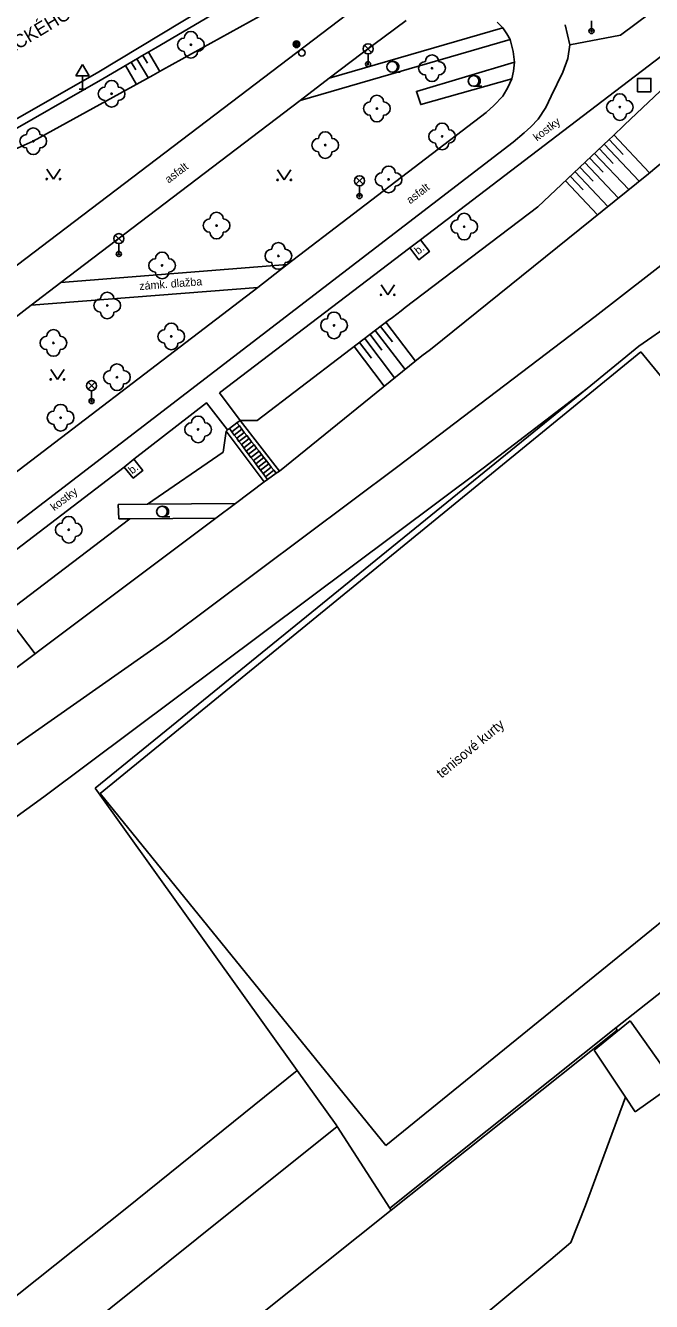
# Model space of a CAD drawing. Extents: x -493753 to -49290, y -1127285 to -112654.
# Drawn here: x -493017.9 to -492971, y -1126683.6 to -1126587.9 of the extents above; entities that cross this region are included whole.
import ezdxf

# ---------------------------------------------------------------- set-up
doc = ezdxf.new("R2010")
doc.units = 0
for name, color, linetype in [('Vrstva 10', 7, 'Continuous'), ('Vrstva 11', 7, 'Continuous'), ('Vrstva 14', 7, 'Continuous'), ('Vrstva 15', 7, 'Continuous'), ('Vrstva 21', 7, 'Continuous'), ('Vrstva 22', 7, 'Continuous'), ('Vrstva 23', 7, 'Continuous'), ('Vrstva 25', 7, 'Continuous'), ('Vrstva 26', 7, 'Continuous'), ('Vrstva 31', 7, 'Continuous'), ('Vrstva 33', 7, 'Continuous'), ('Vrstva 34', 7, 'Continuous'), ('Vrstva 36', 7, 'Continuous'), ('Vrstva 40', 7, 'Continuous'), ('Vrstva 42', 7, 'Continuous'), ('Vrstva 45', 7, 'Continuous'), ('Vrstva 7', 7, 'Continuous'), ('Vrstva 8', 7, 'Continuous')]:
    doc.layers.add(name, color=color, linetype=linetype)

msp = doc.modelspace()

# ---------------------------------------------------------------- linework, layer by layer
at = {"layer": 'Vrstva 10'}
for p, q in [((-493012.38, -1126591.4), (-493000.12, -1126584)), ((-492992.66, -1126590), (-492989.36, -1126587.55)), ((-492967.32, -1126588), (-492988.29, -1126603.99)), ((-492982.54, -1126587.69), (-492982.12, -1126588.12)), ((-492995.12, -1126591.89), (-492992.66, -1126590)), ((-493024.41, -1126598.28), (-493012.38, -1126591.4)), ((-492981.45, -1126591.94), (-492981.73, -1126592.58)), ((-492982.11, -1126593.22), (-492982.78, -1126593.94)), ((-492981.73, -1126592.58), (-492982.11, -1126593.22)), ((-492982.78, -1126593.94), (-492983.37, -1126594.45)), ((-492983.37, -1126594.45), (-492998.28, -1126605.86)), ((-492989.09, -1126604.61), (-493003.34, -1126615.47)), ((-492998.28, -1126605.86), (-493015.22, -1126607.19)), ((-493017.45, -1126608.89), (-493000.48, -1126607.56)), ((-493003.34, -1126615.47), (-493001.79, -1126617.53))]:
    msp.add_line(p, q, dxfattribs=at)
for points in [[(-492985.18, -1126582.35), (-492985.89, -1126582.39), (-492986.62, -1126582.55), (-492988.44, -1126583.3), (-492989.31, -1126583.75), (-492990.15, -1126584.3), (-493020.37, -1126607.3), (-493025.91, -1126611.01)], [(-492977.09, -1126589.39), (-492973.31, -1126588.67), (-492966.57, -1126583.61)], [(-492982.12, -1126588.12), (-492981.82, -1126588.55), (-492981.57, -1126588.99)], [(-492977.09, -1126589.39), (-492977.44, -1126587.89)], [(-492981.57, -1126588.99), (-492981.34, -1126589.88), (-492981.24, -1126590.69)], [(-492981.24, -1126590.69), (-492981.31, -1126591.36), (-492981.45, -1126591.94)], [(-492997.3, -1126593.55), (-492995.12, -1126591.89)], [(-493015.22, -1126607.19), (-492997.3, -1126593.55)], [(-492989.09, -1126604.61), (-492988.41, -1126605.49), (-492987.62, -1126604.88), (-492988.29, -1126603.99)], [(-493000.48, -1126607.56), (-493022.39, -1126624.3)], [(-493034.86, -1126621.08), (-493024.36, -1126614.13), (-493022.77, -1126612.99), (-493017.45, -1126608.89)], [(-492990.89, -1126671.88), (-493012.27, -1126645.51), (-492971.77, -1126612.39)], [(-492971.77, -1126612.39), (-492950.15, -1126638.81), (-492990.89, -1126671.88)], [(-493002.73, -1126618.25), (-493004.31, -1126616.22), (-493009.75, -1126620.45)], [(-493001.79, -1126617.53), (-492998.85, -1126621.33)], [(-493002.83, -1126618.33), (-493002.73, -1126618.25)], [(-492999.99, -1126622.14), (-493002.83, -1126618.33)], [(-493010.47, -1126621.03), (-493009.8, -1126621.86), (-493009.08, -1126621.28), (-493009.75, -1126620.45)], [(-493010.47, -1126621.03), (-493030.36, -1126636.24)], [(-492999.1, -1126621.5), (-492999.75, -1126621.97), (-492999.99, -1126622.14)], [(-492998.85, -1126621.33), (-492999.1, -1126621.5)]]:
    msp.add_lwpolyline(points, dxfattribs=at)
at = {"layer": 'Vrstva 11'}
for p, q in [((-492977.24, -1126590.4), (-492977.09, -1126589.39)), ((-492977.63, -1126591.43), (-492977.24, -1126590.4)), ((-492978.49, -1126593.23), (-492977.63, -1126591.43)), ((-492978.9, -1126594.08), (-492978.49, -1126593.23)), ((-492979.47, -1126594.96), (-492978.9, -1126594.08)), ((-492980.01, -1126595.52), (-492979.47, -1126594.96)), ((-492981.34, -1126596.68), (-492980.51, -1126595.98)), ((-492980.51, -1126595.98), (-492980.01, -1126595.52)), ((-493028.5, -1126632.89), (-492981.34, -1126596.68)), ((-493002.41, -1126618.39), (-493001.84, -1126617.95)), ((-493001.66, -1126618.19), (-493002.23, -1126618.63)), ((-493002.05, -1126618.87), (-493001.48, -1126618.43)), ((-493001.29, -1126618.66), (-493001.88, -1126619.11)), ((-493001.7, -1126619.35), (-493001.11, -1126618.9)), ((-493000.56, -1126619.61), (-493001.16, -1126620.07)), ((-493000.98, -1126620.31), (-493000.38, -1126619.85)), ((-493000.19, -1126620.09), (-493000.8, -1126620.55)), ((-493000.62, -1126620.79), (-493000.01, -1126620.32)), ((-492999.83, -1126620.56), (-493000.44, -1126621.03)), ((-493000.26, -1126621.27), (-492999.64, -1126620.8)), ((-492999.46, -1126621.04), (-493000.08, -1126621.52)), ((-492999.9, -1126621.76), (-492999.27, -1126621.27))]:
    msp.add_line(p, q, dxfattribs=at)
for points in [[(-492988.29, -1126603.99), (-492989.09, -1126604.61)], [(-492998.28, -1126605.86), (-493000.48, -1126607.56)], [(-493017.45, -1126608.89), (-493015.22, -1126607.19)], [(-492983.59, -1126621.11), (-492975.79, -1126615.13)], [(-493002.73, -1126618.25), (-493002.59, -1126618.15), (-493002.03, -1126617.71), (-493001.79, -1126617.53)], [(-493002.59, -1126618.15), (-493002.41, -1126618.39), (-493002.23, -1126618.63), (-493002.05, -1126618.87), (-493001.88, -1126619.11), (-493001.7, -1126619.35), (-493001.52, -1126619.59), (-493001.34, -1126619.83), (-493001.16, -1126620.07), (-493000.98, -1126620.31), (-493000.8, -1126620.55), (-493000.62, -1126620.79), (-493000.44, -1126621.03), (-493000.26, -1126621.27), (-493000.08, -1126621.52), (-492999.9, -1126621.76), (-492999.75, -1126621.97)], [(-492999.1, -1126621.5), (-492999.27, -1126621.27), (-492999.46, -1126621.04), (-492999.64, -1126620.8), (-492999.83, -1126620.56), (-493000.01, -1126620.32), (-493000.19, -1126620.09), (-493000.38, -1126619.85), (-493000.56, -1126619.61), (-493000.74, -1126619.37), (-493000.93, -1126619.14), (-493001.11, -1126618.9), (-493001.29, -1126618.66), (-493001.48, -1126618.43), (-493001.66, -1126618.19), (-493001.84, -1126617.95), (-493002.03, -1126617.71)], [(-493000.93, -1126619.14), (-493001.52, -1126619.59)], [(-493001.34, -1126619.83), (-493000.74, -1126619.37)], [(-493009.75, -1126620.45), (-493010.47, -1126621.03)], [(-493016.5, -1126645.75), (-492983.59, -1126621.11)], [(-493023.17, -1126650.58), (-493016.5, -1126645.75)], [(-492975.26, -1126664.73), (-492972.58, -1126662.53)], [(-492972.58, -1126662.53), (-492969.22, -1126667.25)], [(-492975.26, -1126664.73), (-492972.93, -1126668.26)], [(-493010.29, -1126676.56), (-492997.52, -1126666.25)], [(-492969.7, -1126667.59), (-492972.19, -1126669.37)], [(-492972.93, -1126668.26), (-492975.93, -1126676.38), (-492977.03, -1126679.16), (-492978.53, -1126680.44)], [(-492972.19, -1126669.37), (-492972.93, -1126668.26)], [(-492994.52, -1126670.47), (-493005.05, -1126678.87)], [(-493010.29, -1126676.56), (-493036.05, -1126697.08)], [(-493005.56, -1126688.78), (-492990.47, -1126676.73)], [(-493005.05, -1126678.87), (-493026.67, -1126696.23)], [(-492978.53, -1126680.44), (-492990.17, -1126690.14), (-492997.84, -1126696.72), (-493009.15, -1126700.35), (-493023.88, -1126704.92)]]:
    msp.add_lwpolyline(points, dxfattribs=at)
at = {"layer": 'Vrstva 14'}
for points in [[(-492982.18, -1126573), (-492987.04, -1126578.23), (-492987.89, -1126578.82), (-492988.55, -1126579.27), (-492995.54, -1126584.11), (-492996.22, -1126584.53), (-492998.92, -1126586.45), (-493007.61, -1126591.25), (-493008.3, -1126591.66), (-493017.29, -1126596.61), (-493019.76, -1126597.71), (-493020.5, -1126598.04), (-493023.73, -1126599.48)], [(-493030.36, -1126602.42), (-493021.4, -1126597.27), (-493021.05, -1126597.07), (-493020.7, -1126596.87), (-493020.36, -1126596.67), (-493020.01, -1126596.48), (-493012.09, -1126591.92), (-493009.49, -1126590.41), (-493009.15, -1126590.2), (-493008.8, -1126590), (-493008.46, -1126589.8), (-493008.11, -1126589.6), (-493003.56, -1126586.94)], [(-493001.79, -1126617.53), (-493000.53, -1126617.53), (-492990.7, -1126610.05), (-492990.38, -1126609.81), (-492990.06, -1126609.57), (-492989.74, -1126609.32), (-492989.42, -1126609.08), (-492979.49, -1126601.53), (-492974.16, -1126596.49), (-492973.87, -1126596.22), (-492973.58, -1126595.94), (-492973.29, -1126595.67), (-492973, -1126595.39), (-492966.31, -1126589.07), (-492964.16, -1126588.74)], [(-492998.85, -1126621.33), (-492988.18, -1126612.7), (-492987.54, -1126612.21), (-492971.21, -1126599.04), (-492970.58, -1126598.53), (-492964.89, -1126593.94), (-492962.46, -1126591.8)], [(-493089.62, -1126694.8), (-493086.34, -1126692.42), (-493085.72, -1126691.92), (-493080.25, -1126688), (-493075.98, -1126685.38), (-493052.97, -1126667.87), (-493037.61, -1126656.43), (-493019.04, -1126642.21), (-493007.33, -1126633.97), (-492989.97, -1126620.99), (-492975.2, -1126609.75), (-492962.91, -1126600.21), (-492959, -1126598.1)], [(-493008.74, -1126623.81), (-493003.06, -1126619.91), (-493002.83, -1126618.33)], [(-493002.13, -1126623.75), (-492999.99, -1126622.14)], [(-493003.61, -1126624.85), (-493002.13, -1126623.75)], [(-493068.09, -1126673.3), (-493060.02, -1126667.22), (-493059.41, -1126666.7), (-493048.15, -1126658.29), (-493047.25, -1126657.61), (-493046.61, -1126657.13), (-493034.04, -1126647.7), (-493033.4, -1126647.22), (-493017.32, -1126635.15), (-493016.69, -1126634.67), (-493003.61, -1126624.85)], [(-493010.06, -1126624.9), (-493018.64, -1126631.45), (-493018.96, -1126631.69), (-493019.28, -1126631.93), (-493019.6, -1126632.17), (-493019.91, -1126632.42), (-493029.29, -1126639.56)]]:
    msp.add_lwpolyline(points, dxfattribs=at)
at = {"layer": 'Vrstva 15'}
for p, q in [((-493009.52, -1126590.42), (-493008.67, -1126591.87)), ((-493009.09, -1126590.17), (-493008.74, -1126590.75)), ((-493008.65, -1126589.92), (-493007.8, -1126591.37)), ((-493010.38, -1126590.93), (-493009.55, -1126592.35)), ((-493009.95, -1126590.67), (-493009.61, -1126591.25)), ((-492973.79, -1126596.14), (-492971.12, -1126598.97)), ((-492974.52, -1126596.83), (-492971.9, -1126599.6)), ((-492974.16, -1126596.49), (-492973.1, -1126597.61)), ((-492975.61, -1126597.86), (-492974.59, -1126598.93)), ((-492975.25, -1126597.52), (-492972.68, -1126600.23)), ((-492974.88, -1126597.17), (-492973.85, -1126598.27)), ((-492976.7, -1126598.89), (-492974.25, -1126601.49)), ((-492976.34, -1126598.55), (-492975.34, -1126599.6)), ((-492975.97, -1126598.2), (-492973.47, -1126600.86)), ((-492977.43, -1126599.58), (-492975.03, -1126602.12)), ((-492977.06, -1126599.23), (-492976.09, -1126600.26)), ((-492991.27, -1126610.49), (-492990.38, -1126611.65)), ((-492990.87, -1126610.18), (-492988.66, -1126613.09)), ((-492992.46, -1126611.39), (-492990.22, -1126614.34)), ((-492992.06, -1126611.09), (-492991.17, -1126612.27)), ((-492991.67, -1126610.79), (-492989.44, -1126613.71)), ((-492993.26, -1126612), (-492991, -1126614.97)), ((-492992.86, -1126611.7), (-492991.96, -1126612.88)), ((-493019.42, -1126632.04), (-493017.15, -1126635.02))]:
    msp.add_line(p, q, dxfattribs=at)
at = {"layer": 'Vrstva 21'}
msp.add_line((-492982.12, -1126588.12), (-492995.12, -1126591.89), dxfattribs=at)
msp.add_lwpolyline([(-492981.24, -1126590.69), (-492988.59, -1126592.88), (-492988.26, -1126593.86), (-492981.45, -1126591.94)], dxfattribs=at)
at = {"layer": 'Vrstva 22'}
for centre in [(-493005.48, -1126589.38), (-492987.42, -1126591.14), (-493011.42, -1126593.05), (-492991.55, -1126594.16), (-492973.35, -1126594.05), (-493017.29, -1126596.61), (-492995.42, -1126596.9), (-492986.66, -1126596.25), (-492990.67, -1126599.47), (-493003.56, -1126602.93), (-492985.01, -1126603.01), (-492998.93, -1126605.21), (-493007.64, -1126605.92), (-493011.75, -1126608.92), (-492994.76, -1126610.41), (-493006.95, -1126611.24), (-493015.78, -1126611.73), (-493011.02, -1126614.3), (-493015.24, -1126617.33), (-493004.94, -1126618.21), (-493014.63, -1126625.73)]:
    msp.add_circle(centre, 0.05, dxfattribs=at)
for centre, start, end in [((-493005.48, -1126588.88), 0, 180), ((-493005.98, -1126589.38), 90, 270), ((-493004.98, -1126589.38), 270, 90), ((-493005.48, -1126589.88), 180, 0), ((-492987.42, -1126590.64), 0, 180), ((-492987.92, -1126591.14), 90, 270), ((-492986.92, -1126591.14), 270, 90), ((-493011.42, -1126592.55), 0, 180), ((-492987.42, -1126591.64), 180, 0), ((-493011.92, -1126593.05), 90, 270), ((-493010.92, -1126593.05), 270, 90), ((-492991.55, -1126593.66), 0, 180), ((-492973.35, -1126593.55), 0, 180), ((-493011.42, -1126593.55), 180, 0), ((-492992.05, -1126594.16), 90, 270), ((-492991.05, -1126594.16), 270, 90), ((-492973.85, -1126594.05), 90, 270), ((-492972.85, -1126594.05), 270, 90), ((-492991.55, -1126594.66), 180, 0), ((-492973.35, -1126594.55), 180, 0), ((-493017.79, -1126596.61), 90, 270), ((-493017.29, -1126596.11), 0, 180), ((-493016.79, -1126596.61), 270, 90), ((-492995.42, -1126596.4), 0, 180), ((-492987.16, -1126596.25), 90, 270), ((-492986.66, -1126595.75), 0, 180), ((-492986.16, -1126596.25), 270, 90), ((-493017.29, -1126597.11), 180, 0), ((-492995.92, -1126596.9), 90, 270), ((-492994.92, -1126596.9), 270, 90), ((-492986.66, -1126596.75), 180, 0), ((-492995.42, -1126597.4), 180, 0), ((-492991.17, -1126599.47), 90, 270), ((-492990.67, -1126598.97), 0, 180), ((-492990.17, -1126599.47), 270, 90), ((-492990.67, -1126599.97), 180, 0), ((-493004.06, -1126602.93), 90, 270), ((-493003.56, -1126602.43), 0, 180), ((-493003.06, -1126602.93), 270, 90), ((-492985.51, -1126603.01), 90, 270), ((-492985.01, -1126602.51), 0, 180), ((-492984.51, -1126603.01), 270, 90), ((-493003.56, -1126603.43), 180, 0), ((-492985.01, -1126603.51), 180, 0), ((-492999.43, -1126605.21), 90, 270), ((-492998.93, -1126604.71), 0, 180), ((-492998.43, -1126605.21), 270, 90), ((-493008.14, -1126605.92), 90, 270), ((-493007.64, -1126605.42), 0, 180), ((-493007.14, -1126605.92), 270, 90), ((-492998.93, -1126605.71), 180, 0), ((-493007.64, -1126606.42), 180, 0), ((-493012.25, -1126608.92), 90, 270), ((-493011.75, -1126608.42), 0, 180), ((-493011.25, -1126608.92), 270, 90), ((-493011.75, -1126609.42), 180, 0), ((-492994.76, -1126609.91), 0, 180), ((-493006.95, -1126610.74), 0, 180), ((-492995.26, -1126610.41), 90, 270), ((-492994.26, -1126610.41), 270, 90), ((-493016.28, -1126611.73), 90, 270), ((-493015.78, -1126611.23), 0, 180), ((-493015.28, -1126611.73), 270, 90), ((-493007.45, -1126611.24), 90, 270), ((-493006.45, -1126611.24), 270, 90), ((-492994.76, -1126610.91), 180, 0), ((-493015.78, -1126612.23), 180, 0), ((-493006.95, -1126611.74), 180, 0), ((-493011.02, -1126613.8), 0, 180), ((-493011.52, -1126614.3), 90, 270), ((-493010.52, -1126614.3), 270, 90), ((-493011.02, -1126614.8), 180, 0), ((-493015.74, -1126617.33), 90, 270), ((-493015.24, -1126616.83), 0, 180), ((-493014.74, -1126617.33), 270, 90), ((-493015.24, -1126617.83), 180, 0), ((-493005.44, -1126618.21), 90, 270), ((-493004.94, -1126617.71), 0, 180), ((-493004.44, -1126618.21), 270, 90), ((-493004.94, -1126618.71), 180, 0), ((-493014.63, -1126625.23), 0, 180), ((-493015.13, -1126625.73), 90, 270), ((-493014.13, -1126625.73), 270, 90), ((-493014.63, -1126626.23), 180, 0)]:
    msp.add_arc(centre, 0.5, start, end, dxfattribs=at)
at = {"layer": 'Vrstva 23'}
for p, q in [((-492997.3, -1126593.55), (-492981.57, -1126588.99)), ((-493010.89, -1126624.91), (-493010.92, -1126623.83))]:
    msp.add_line(p, q, dxfattribs=at)
for points in [[(-493010.92, -1126623.83), (-493008.74, -1126623.81), (-493002.13, -1126623.75)], [(-493010.89, -1126624.91), (-493010.06, -1126624.9), (-493003.61, -1126624.85)]]:
    msp.add_lwpolyline(points, dxfattribs=at)
at = {"layer": 'Vrstva 25'}
for radius in [0.25, 0.158, 0.05]:
    msp.add_circle((-492997.57, -1126589.34), radius, dxfattribs=at)
at = {"layer": 'Vrstva 26'}
msp.add_lwpolyline([(-492972.02, -1126592.9), (-492971.02, -1126592.9), (-492971.02, -1126591.9), (-492972.02, -1126591.9)], close=True, dxfattribs=at)
at = {"layer": 'Vrstva 31'}
msp.add_circle((-492997.17, -1126589.98), 0.25, dxfattribs=at)
at = {"layer": 'Vrstva 33'}
for p, q in [((-492975.47, -1126588.35), (-492975.47, -1126587.575)), ((-492992.475, -1126589.415), (-492991.945, -1126589.945)), ((-492992.475, -1126589.945), (-492991.945, -1126589.415)), ((-492992.21, -1126590.83), (-492992.21, -1126590.055)), ((-492993.115, -1126599.305), (-492992.585, -1126599.835)), ((-492993.115, -1126599.835), (-492992.585, -1126599.305)), ((-492992.85, -1126600.72), (-492992.85, -1126599.945)), ((-493011.145, -1126603.645), (-493010.615, -1126604.175)), ((-493011.145, -1126604.175), (-493010.615, -1126603.645)), ((-493010.88, -1126605.06), (-493010.88, -1126604.285)), ((-493013.185, -1126614.665), (-493012.655, -1126615.195)), ((-493013.185, -1126615.195), (-493012.655, -1126614.665)), ((-493012.92, -1126616.08), (-493012.92, -1126615.305))]:
    msp.add_line(p, q, dxfattribs=at)
for centre, radius in [((-492975.47, -1126588.35), 0.19), ((-492975.47, -1126588.35), 0.05), ((-492992.21, -1126589.68), 0.375), ((-492992.21, -1126590.83), 0.19), ((-492992.21, -1126590.83), 0.05), ((-492992.85, -1126599.57), 0.375), ((-492992.85, -1126600.72), 0.19), ((-492992.85, -1126600.72), 0.05), ((-493010.88, -1126603.91), 0.375), ((-493010.88, -1126605.06), 0.19), ((-493010.88, -1126605.06), 0.05), ((-493012.92, -1126614.93), 0.375), ((-493012.92, -1126616.08), 0.19), ((-493012.92, -1126616.08), 0.05)]:
    msp.add_circle(centre, radius, dxfattribs=at)
at = {"layer": 'Vrstva 34'}
for p, q in [((-493014.1, -1126591.7), (-493013.6, -1126590.85)), ((-493013.6, -1126590.85), (-493013.1, -1126591.7)), ((-493014.1, -1126591.7), (-493013.1, -1126591.7)), ((-493013.6, -1126592.7), (-493013.6, -1126591.7)), ((-493013.85, -1126592.7), (-493013.35, -1126592.7))]:
    msp.add_line(p, q, dxfattribs=at)
at = {"layer": 'Vrstva 36'}
for p, q in [((-492990.4, -1126591.43), (-492990.3, -1126591.43)), ((-492990.3, -1126591.43), (-492989.8, -1126591.43)), ((-492984.3, -1126592.49), (-492984.2, -1126592.49)), ((-492984.2, -1126592.49), (-492983.7, -1126592.49)), ((-493016.28, -1126598.69), (-493015.78, -1126599.44)), ((-493015.78, -1126599.44), (-493015.28, -1126598.69)), ((-492998.99, -1126598.76), (-492998.49, -1126599.51)), ((-492998.49, -1126599.51), (-492997.99, -1126598.76)), ((-492991.24, -1126607.37), (-492990.74, -1126608.12)), ((-492990.74, -1126608.12), (-492990.24, -1126607.37)), ((-493015.98, -1126613.71), (-493015.48, -1126614.46)), ((-493015.48, -1126614.46), (-493014.98, -1126613.71)), ((-493007.65, -1126624.77), (-493007.55, -1126624.77)), ((-493007.55, -1126624.77), (-493007.05, -1126624.77))]:
    msp.add_line(p, q, dxfattribs=at)
for centre, radius in [((-492990.4, -1126591.03), 0.4), ((-492984.3, -1126592.09), 0.4), ((-493016.28, -1126599.44), 0.05), ((-493015.28, -1126599.44), 0.05), ((-492998.99, -1126599.51), 0.05), ((-492997.99, -1126599.51), 0.05), ((-492991.24, -1126608.12), 0.05), ((-492990.24, -1126608.12), 0.05), ((-493015.98, -1126614.46), 0.05), ((-493014.98, -1126614.46), 0.05), ((-493007.65, -1126624.37), 0.4)]:
    msp.add_circle(centre, radius, dxfattribs=at)
for centre in [(-492990.3, -1126591.03), (-492984.2, -1126592.09), (-493007.55, -1126624.37)]:
    msp.add_arc(centre, 0.4, 259.69515, 97.18076, dxfattribs=at)
at = {"layer": 'Vrstva 7'}
for p, q in [((-492971.92, -1126611.98), (-492969.41, -1126610.23)), ((-492960.63, -1126652.77), (-492973.66, -1126663.07)), ((-492990.59, -1126676.57), (-492973.66, -1126663.07)), ((-492973.54, -1126663.23), (-492973.66, -1126663.07)), ((-492990.47, -1126676.73), (-492973.54, -1126663.23)), ((-492990.47, -1126676.73), (-492990.59, -1126676.57))]:
    msp.add_line(p, q, dxfattribs=at)
for points in [[(-493012.65, -1126645.09), (-492975.79, -1126615.13), (-492971.92, -1126611.98)], [(-492994.6, -1126670.34), (-492997.52, -1126666.25), (-493012.65, -1126645.09)]]:
    msp.add_lwpolyline(points, dxfattribs=at)
at = {"layer": 'Vrstva 8'}
msp.add_lwpolyline([(-492990.59, -1126676.57), (-492994.52, -1126670.47), (-492994.6, -1126670.34)], dxfattribs=at)

# ---------------------------------------------------------------- texts
at = {"layer": 'Vrstva 40'}
for s, rotation, p in [('kostky', 37.40536, (-492979.556, -1126596.631)), ('asfalt', 37.27706, (-493007.15, -1126599.79)), ('asfalt', 37.51748, (-492989.057, -1126601.344)), ('b.', 38.37886, (-492988.447, -1126605.138)), ('zámk. dlažba', 4.48132, (-493009.328, -1126607.77)), ('b.', 38.37886, (-493009.877, -1126621.588)), ('kostky', 37.40536, (-493015.716, -1126624.351))]:
    msp.add_text(s, height=0.6, rotation=rotation, dxfattribs=at).set_placement(p)
at = {"layer": 'Vrstva 42'}
msp.add_text('tenisové kurty', height=0.75, rotation=39.50521, dxfattribs=at).set_placement((-492986.705, -1126644.391))
at = {"layer": 'Vrstva 45'}
msp.add_text('PALACKÉHO', height=1, rotation=31.12856, dxfattribs=at).set_placement((-493021.351, -1126591.524))

doc.saveas('drawing.dxf')
